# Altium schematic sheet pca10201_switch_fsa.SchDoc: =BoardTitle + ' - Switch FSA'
size A3; Organization: Nordic Semiconductor; DocumentNumber: 9; SheetNumber: 9; SheetTotal: 10; CompanyName: Nordic Semiconductor; DocumentSize: A4
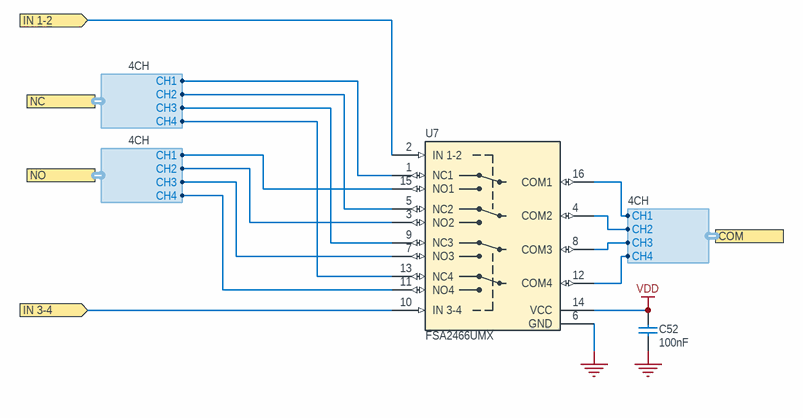
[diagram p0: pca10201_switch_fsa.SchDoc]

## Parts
C52  100nF  [CAPC0603X03L_C]
U7  FSA2466UMX  [XQFN40P180X260X50-16N]

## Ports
COM (harness 4CH), IN 1-2 (in), IN 3-4 (in), NC (harness 4CH), NO (harness 4CH)

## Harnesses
4CH: CH1, CH2, CH3, CH4

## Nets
GND: C52.2 U7.6(GND)
VDD: C52.1 U7.14(VCC)
IN 1-2: U7.2(IN_1-2) ; port IN 1-2
IN 3-4: U7.10(IN_3-4) ; port IN 3-4
NetU7_1: U7.1(NC1) ; port NC.CH1
NetU7_3: U7.3(NO2) ; port NO.CH2
NetU7_4: U7.4(COM2) ; port COM.CH2
NetU7_5: U7.5(NC2) ; port NC.CH2
NetU7_7: U7.7(NO3) ; port NO.CH3
NetU7_8: U7.8(COM3) ; port COM.CH3
NetU7_9: U7.9(NC3) ; port NC.CH3
NetU7_11: U7.11(NO4) ; port NO.CH4
NetU7_12: U7.12(COM4) ; port COM.CH4
NetU7_13: U7.13(NC4) ; port NC.CH4
NetU7_15: U7.15(NO1) ; port NO.CH1
NetU7_16: U7.16(COM1) ; port COM.CH1

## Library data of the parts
C52 = C0201-100n: Capacitor, X5R, ±10%, 100nF, 16V; Manufacturer: N.A.; Part number IPS: 00000001248, 00000002505; Part number Norautron: 262071862; Part number NEMS: 100200078; Pad Count: 2; Component Status: Active
U7 = FSA2466UMX: Data / Audio Low-Voltage Dual DPDT Analog Switch; Manufacturer: ON Semiconductor; Part number IPS: 00000009986; Part number Norautron: 26500608; Part number NEMS: 101900422; Note: N.A.; Artikkelnr Noca: 15070069; Pad Count: 16; Component Status: Active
